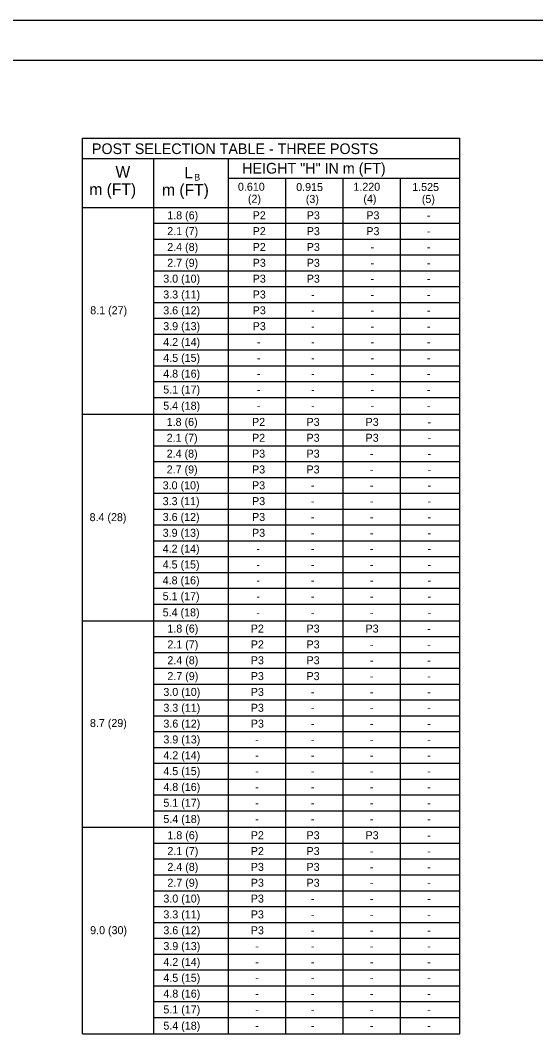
# Model space of a CAD drawing. Extents: x -1958 to 628, y -879 to 309.
# Drawn here: x -63.2 to 130.1, y -71.3 to 309.4 of the extents above; entities that cross this region are included whole.
import ezdxf

# ---------------------------------------------------------------- set-up
doc = ezdxf.new("R2010")
doc.units = 0
for name, color, linetype in [('1', 7, 'Continuous'), ('2', 7, 'Continuous'), ('PLT-BNDY', 7, 'Continuous')]:
    doc.layers.add(name, color=color, linetype=linetype)

msp = doc.modelspace()

# ---------------------------------------------------------------- linework, layer by layer
at = {"layer": '1'}
for p, q in [((-236.39, 294.44), (549.61, 294.44)), ((-39.86, 239.28), (-39.86, 265.3)), ((-39.86, 265.3), (101.61, 265.3)), ((101.61, 239.28), (101.61, 265.3)), ((-39.86, 257.63), (101.61, 257.63)), ((-13.06, 239.28), (-13.06, 257.63)), ((14.94, 239.28), (14.94, 257.63)), ((36.44, -70.68), (36.44, 250.28)), ((57.94, -70.68), (57.94, 250.28)), ((79.44, -70.68), (79.44, 250.28)), ((-39.86, -70.68), (-39.86, 239.28)), ((-39.86, 239.28), (101.61, 239.28)), ((-13.06, -70.68), (-13.06, 239.28)), ((14.94, -70.68), (14.94, 239.28)), ((101.61, -70.68), (101.61, 239.28))]:
    msp.add_line(p, q, dxfattribs=at)
at = {"layer": '2'}
for p, q in [((14.94, 250.28), (101.61, 250.28)), ((-13.06, 233.34), (101.61, 233.34)), ((-13.06, 227.4), (101.61, 227.4)), ((-13.06, 221.46), (101.61, 221.46)), ((53.29, 221.46), (97.57, 221.46)), ((-13.06, 215.52), (101.61, 215.52)), ((53.29, 215.52), (97.57, 215.52)), ((-13.06, 209.58), (101.61, 209.58)), ((53.29, 209.58), (97.57, 209.58)), ((-13.06, 203.64), (101.61, 203.64)), ((53.29, 203.64), (97.57, 203.64)), ((-13.06, 197.7), (101.61, 197.7)), ((53.29, 197.7), (97.57, 197.7)), ((-13.06, 191.76), (101.61, 191.76)), ((53.29, 191.76), (97.57, 191.76)), ((-13.06, 185.82), (101.61, 185.82)), ((53.29, 185.82), (97.57, 185.82)), ((-13.06, 179.88), (101.61, 179.88)), ((53.29, 179.88), (97.57, 179.88)), ((-13.06, 173.94), (101.61, 173.94)), ((53.29, 173.94), (97.57, 173.94)), ((-13.06, 168), (101.61, 168)), ((-39.86, 161.79), (101.61, 161.79)), ((-13.06, 155.85), (101.61, 155.85)), ((-13.06, 149.91), (101.61, 149.91)), ((53.29, 149.91), (97.57, 149.91)), ((-13.06, 143.97), (101.61, 143.97)), ((-13.06, 138.03), (101.61, 138.03)), ((53.29, 138.03), (97.57, 138.03)), ((-13.06, 132.09), (101.61, 132.09)), ((53.29, 132.09), (97.57, 132.09)), ((-13.06, 126.15), (101.61, 126.15)), ((-13.06, 120.21), (101.61, 120.21)), ((-13.06, 114.27), (101.61, 114.27)), ((-13.06, 108.33), (101.61, 108.33)), ((-13.06, 102.39), (101.61, 102.39)), ((-13.06, 96.45), (101.61, 96.45)), ((-13.06, 90.51), (101.61, 90.51)), ((-39.86, 84.3), (101.61, 84.3)), ((-13.06, 78.36), (101.61, 78.36)), ((-13.06, 72.42), (101.61, 72.42)), ((-13.06, 66.48), (101.61, 66.48)), ((97.57, 66.48), (101.61, 66.48)), ((-13.06, 60.54), (101.61, 60.54)), ((-13.06, 54.6), (101.61, 54.6)), ((-13.06, 48.66), (101.61, 48.66)), ((-13.06, 42.72), (101.61, 42.72)), ((-13.06, 36.78), (101.61, 36.78)), ((-13.06, 30.84), (101.61, 30.84)), ((-13.06, 24.9), (101.61, 24.9)), ((-13.06, 18.96), (101.61, 18.96)), ((-13.06, 13.02), (101.61, 13.02)), ((-39.86, 6.81), (101.61, 6.81)), ((-13.06, 0.87), (101.61, 0.87)), ((-13.06, -5.07), (101.61, -5.07)), ((-13.06, -11.01), (101.61, -11.01)), ((-13.06, -16.95), (101.61, -16.95)), ((-13.06, -22.89), (101.61, -22.89)), ((-13.06, -28.83), (101.61, -28.83)), ((-13.06, -34.77), (101.61, -34.77)), ((-13.06, -40.71), (101.61, -40.71)), ((-13.06, -46.65), (101.61, -46.65)), ((-13.06, -52.59), (101.61, -52.59)), ((-13.06, -58.53), (101.61, -58.53)), ((-13.06, -64.47), (101.61, -64.47)), ((-39.86, -70.68), (101.61, -70.68))]:
    msp.add_line(p, q, dxfattribs=at)
at = {"layer": 'PLT-BNDY'}
msp.add_lwpolyline([(-276.39, 309.44), (564.61, 309.44), (564.61, -284.56), (-276.39, -284.56)], close=True, dxfattribs=at)

# ---------------------------------------------------------------- texts
at = {"layer": '1'}
for s, height, p in [('POST SELECTION TABLE - THREE POSTS', 4.003, (-36.3, 259.28)), ('HEIGHT "H" IN m (FT)', 4.003, (20.05, 251.96)), ('W', 4.37, (-27.47, 250.43)), ('L', 4.3, (-1.67, 250.16)), ('B', 2.5, (2.03, 249.33)), ('m (FT)', 4.375, (-37.28, 243.87)), ('m (FT)', 4.375, (-10.02, 243.7)), ('0.610', 3, (18.43, 245.52)), ('0.915', 3, (40.27, 245.42)), ('1.220', 3, (61.72, 245.52)), ('1.525', 3, (83.77, 245.42)), ('(2)', 3, (22.18, 241.02)), ('(3)', 3, (43.88, 240.92)), ('(4)', 3, (65.46, 241.02)), ('(5)', 3, (87.38, 240.92))]:
    msp.add_text(s, height=height, dxfattribs=at).set_placement(p)
at = {"layer": '2'}
for s, p in [('1.8 (6)', (-8.07, 234.82)), ('P2', (23.96, 234.82)), ('P3', (44.23, 234.82)), ('P3', (66.57, 234.82)), ('-', (89.28, 234.82)), ('2.1 (7)', (-8.07, 228.88)), ('P2', (23.96, 228.88)), ('P3', (44.23, 228.88)), ('P3', (66.57, 228.88)), ('-', (89.28, 228.88)), ('2.4 (8)', (-8.07, 222.94)), ('P2', (23.96, 222.94)), ('P3', (44.23, 222.94)), ('-', (68.19, 222.94)), ('-', (89.28, 222.94)), ('2.7 (9)', (-8.07, 217)), ('P3', (23.96, 217)), ('P3', (44.23, 217)), ('-', (68.19, 217)), ('-', (89.28, 217)), ('3.0 (10)', (-9.57, 211.06)), ('P3', (23.96, 211.06)), ('P3', (44.23, 211.06)), ('-', (68.19, 211.06)), ('-', (89.28, 211.06)), ('3.3 (11)', (-9.57, 205.12)), ('P3', (23.96, 205.12)), ('-', (45.84, 205.12)), ('-', (68.19, 205.12)), ('-', (89.28, 205.12)), ('8.1 (27)', (-36.94, 199.21)), ('3.6 (12)', (-9.57, 199.18)), ('P3', (23.96, 199.18)), ('-', (45.84, 199.18)), ('-', (68.19, 199.18)), ('-', (89.28, 199.18)), ('3.9 (13)', (-9.57, 193.24)), ('P3', (23.96, 193.24)), ('-', (45.84, 193.24)), ('-', (68.19, 193.24)), ('-', (89.28, 193.24)), ('4.2 (14)', (-9.57, 187.3)), ('-', (25.58, 187.3)), ('-', (45.84, 187.3)), ('-', (68.19, 187.3)), ('-', (89.28, 187.3)), ('4.5 (15)', (-9.57, 181.36)), ('-', (25.58, 181.36)), ('-', (45.84, 181.36)), ('-', (68.19, 181.36)), ('-', (89.28, 181.36)), ('4.8 (16)', (-9.57, 175.42)), ('-', (25.58, 175.42)), ('-', (45.84, 175.42)), ('-', (68.19, 175.42)), ('-', (89.28, 175.42)), ('5.1 (17)', (-9.57, 169.48)), ('-', (25.58, 169.48)), ('-', (45.84, 169.48)), ('-', (68.19, 169.48)), ('-', (89.28, 169.48)), ('5.4 (18)', (-9.57, 163.4)), ('-', (25.58, 163.4)), ('-', (45.84, 163.4)), ('-', (68.19, 163.4)), ('-', (89.28, 163.4)), ('1.8 (6)', (-8.28, 157.33)), ('P2', (23.72, 157.33)), ('P3', (44.15, 157.33)), ('P3', (66.29, 157.33)), ('-', (89.49, 157.33)), ('2.1 (7)', (-8.28, 151.39)), ('P2', (23.72, 151.39)), ('P3', (44.15, 151.39)), ('P3', (66.29, 151.39)), ('-', (89.49, 151.39)), ('2.4 (8)', (-8.28, 145.45)), ('P3', (23.72, 145.45)), ('P3', (44.15, 145.45)), ('-', (67.91, 145.45)), ('-', (89.49, 145.45)), ('2.7 (9)', (-8.28, 139.51)), ('P3', (23.72, 139.51)), ('P3', (44.15, 139.51)), ('-', (67.91, 139.51)), ('-', (89.49, 139.51)), ('3.0 (10)', (-9.78, 133.57)), ('P3', (23.72, 133.57)), ('-', (45.77, 133.57)), ('-', (67.91, 133.57)), ('-', (89.49, 133.57)), ('3.3 (11)', (-9.78, 127.63)), ('P3', (23.72, 127.63)), ('-', (45.77, 127.63)), ('-', (67.91, 127.63)), ('-', (89.49, 127.63)), ('8.4 (28)', (-37.19, 121.62)), ('3.6 (12)', (-9.78, 121.69)), ('P3', (23.72, 121.69)), ('-', (45.77, 121.69)), ('-', (67.91, 121.69)), ('-', (89.49, 121.69)), ('3.9 (13)', (-9.78, 115.75)), ('P3', (23.72, 115.75)), ('-', (45.77, 115.75)), ('-', (67.91, 115.75)), ('-', (89.49, 115.75)), ('4.2 (14)', (-9.78, 109.81)), ('-', (25.34, 109.81)), ('-', (45.77, 109.81)), ('-', (67.91, 109.81)), ('-', (89.49, 109.81)), ('4.5 (15)', (-9.78, 103.87)), ('-', (25.34, 103.87)), ('-', (45.77, 103.87)), ('-', (67.91, 103.87)), ('-', (89.49, 103.87)), ('4.8 (16)', (-9.78, 97.93)), ('-', (25.34, 97.93)), ('-', (45.77, 97.93)), ('-', (67.91, 97.93)), ('-', (89.49, 97.93)), ('5.1 (17)', (-9.78, 91.99)), ('-', (25.34, 91.99)), ('-', (45.77, 91.99)), ('-', (67.91, 91.99)), ('-', (89.49, 91.99)), ('5.4 (18)', (-9.78, 85.91)), ('-', (25.34, 85.91)), ('-', (45.77, 85.91)), ('-', (67.91, 85.91)), ('-', (89.49, 85.91)), ('1.8 (6)', (-8.02, 79.84)), ('P2', (23.25, 79.84)), ('P3', (44.15, 79.84)), ('P3', (66.27, 79.84)), ('-', (89.39, 79.84)), ('2.1 (7)', (-8.02, 73.9)), ('P2', (23.25, 73.9)), ('P3', (44.15, 73.9)), ('-', (67.89, 73.9)), ('-', (89.39, 73.9)), ('2.4 (8)', (-8.02, 67.96)), ('P3', (23.25, 67.96)), ('P3', (44.15, 67.96)), ('-', (67.89, 67.96)), ('-', (89.39, 67.96)), ('2.7 (9)', (-8.02, 62.02)), ('P3', (23.25, 62.02)), ('P3', (44.15, 62.02)), ('-', (67.89, 62.02)), ('-', (89.39, 62.02)), ('3.0 (10)', (-9.52, 56.08)), ('P3', (23.25, 56.08)), ('-', (45.77, 56.08)), ('-', (67.89, 56.08)), ('-', (89.39, 56.08)), ('3.3 (11)', (-9.52, 50.14)), ('P3', (23.25, 50.14)), ('-', (45.77, 50.14)), ('-', (67.89, 50.14)), ('-', (89.39, 50.14)), ('8.7 (29)', (-37.05, 44.43)), ('3.6 (12)', (-9.52, 44.2)), ('P3', (23.25, 44.2)), ('-', (45.77, 44.2)), ('-', (67.89, 44.2)), ('-', (89.39, 44.2)), ('3.9 (13)', (-9.52, 38.26)), ('-', (24.87, 38.26)), ('-', (45.77, 38.26)), ('-', (67.89, 38.26)), ('-', (89.39, 38.26)), ('4.2 (14)', (-9.52, 32.32)), ('-', (24.87, 32.32)), ('-', (45.77, 32.32)), ('-', (67.89, 32.32)), ('-', (89.39, 32.32)), ('4.5 (15)', (-9.52, 26.38)), ('-', (24.87, 26.38)), ('-', (45.77, 26.38)), ('-', (67.89, 26.38)), ('-', (89.39, 26.38)), ('4.8 (16)', (-9.52, 20.44)), ('-', (24.87, 20.44)), ('-', (45.77, 20.44)), ('-', (67.89, 20.44)), ('-', (89.39, 20.44)), ('5.1 (17)', (-9.52, 14.5)), ('-', (24.87, 14.5)), ('-', (45.77, 14.5)), ('-', (67.89, 14.5)), ('-', (89.39, 14.5)), ('5.4 (18)', (-9.52, 8.42)), ('-', (24.87, 8.42)), ('-', (45.77, 8.42)), ('-', (67.89, 8.42)), ('-', (89.39, 8.42)), ('1.8 (6)', (-8.02, 2.35)), ('P2', (23.25, 2.35)), ('P3', (44.15, 2.35)), ('P3', (66.27, 2.35)), ('-', (89.39, 2.35)), ('2.1 (7)', (-8.02, -3.59)), ('P2', (23.25, -3.59)), ('P3', (44.15, -3.59)), ('-', (67.89, -3.59)), ('-', (89.39, -3.59)), ('2.4 (8)', (-8.02, -9.53)), ('P3', (23.25, -9.53)), ('P3', (44.15, -9.53)), ('-', (67.89, -9.53)), ('-', (89.39, -9.53)), ('2.7 (9)', (-8.02, -15.47)), ('P3', (23.25, -15.47)), ('P3', (44.15, -15.47)), ('-', (67.89, -15.47)), ('-', (89.39, -15.47)), ('3.0 (10)', (-9.52, -21.41)), ('P3', (23.25, -21.41)), ('-', (45.77, -21.41)), ('-', (67.89, -21.41)), ('-', (89.39, -21.41)), ('3.3 (11)', (-9.52, -27.35)), ('P3', (23.25, -27.35)), ('-', (45.77, -27.35)), ('-', (67.89, -27.35)), ('-', (89.39, -27.35)), ('9.0 (30)', (-36.97, -33.26)), ('3.6 (12)', (-9.52, -33.29)), ('P3', (23.25, -33.29)), ('-', (45.77, -33.29)), ('-', (67.89, -33.29)), ('-', (89.39, -33.29)), ('3.9 (13)', (-9.52, -39.23)), ('-', (24.87, -39.23)), ('-', (45.77, -39.23)), ('-', (67.89, -39.23)), ('-', (89.39, -39.23)), ('4.2 (14)', (-9.52, -45.17)), ('-', (24.87, -45.17)), ('-', (45.77, -45.17)), ('-', (67.89, -45.17)), ('-', (89.39, -45.17)), ('4.5 (15)', (-9.52, -51.11)), ('-', (24.87, -51.11)), ('-', (45.77, -51.11)), ('-', (67.89, -51.11)), ('-', (89.39, -51.11)), ('4.8 (16)', (-9.52, -57.05)), ('-', (24.87, -57.05)), ('-', (45.77, -57.05)), ('-', (67.89, -57.05)), ('-', (89.39, -57.05)), ('5.1 (17)', (-9.52, -62.99)), ('-', (24.87, -62.99)), ('-', (45.77, -62.99)), ('-', (67.89, -62.99)), ('-', (89.39, -62.99)), ('5.4 (18)', (-9.52, -69.07)), ('-', (24.87, -69.07)), ('-', (45.77, -69.07)), ('-', (67.89, -69.07)), ('-', (89.39, -69.07))]:
    msp.add_text(s, height=3, dxfattribs=at).set_placement(p)

doc.saveas('drawing.dxf')
